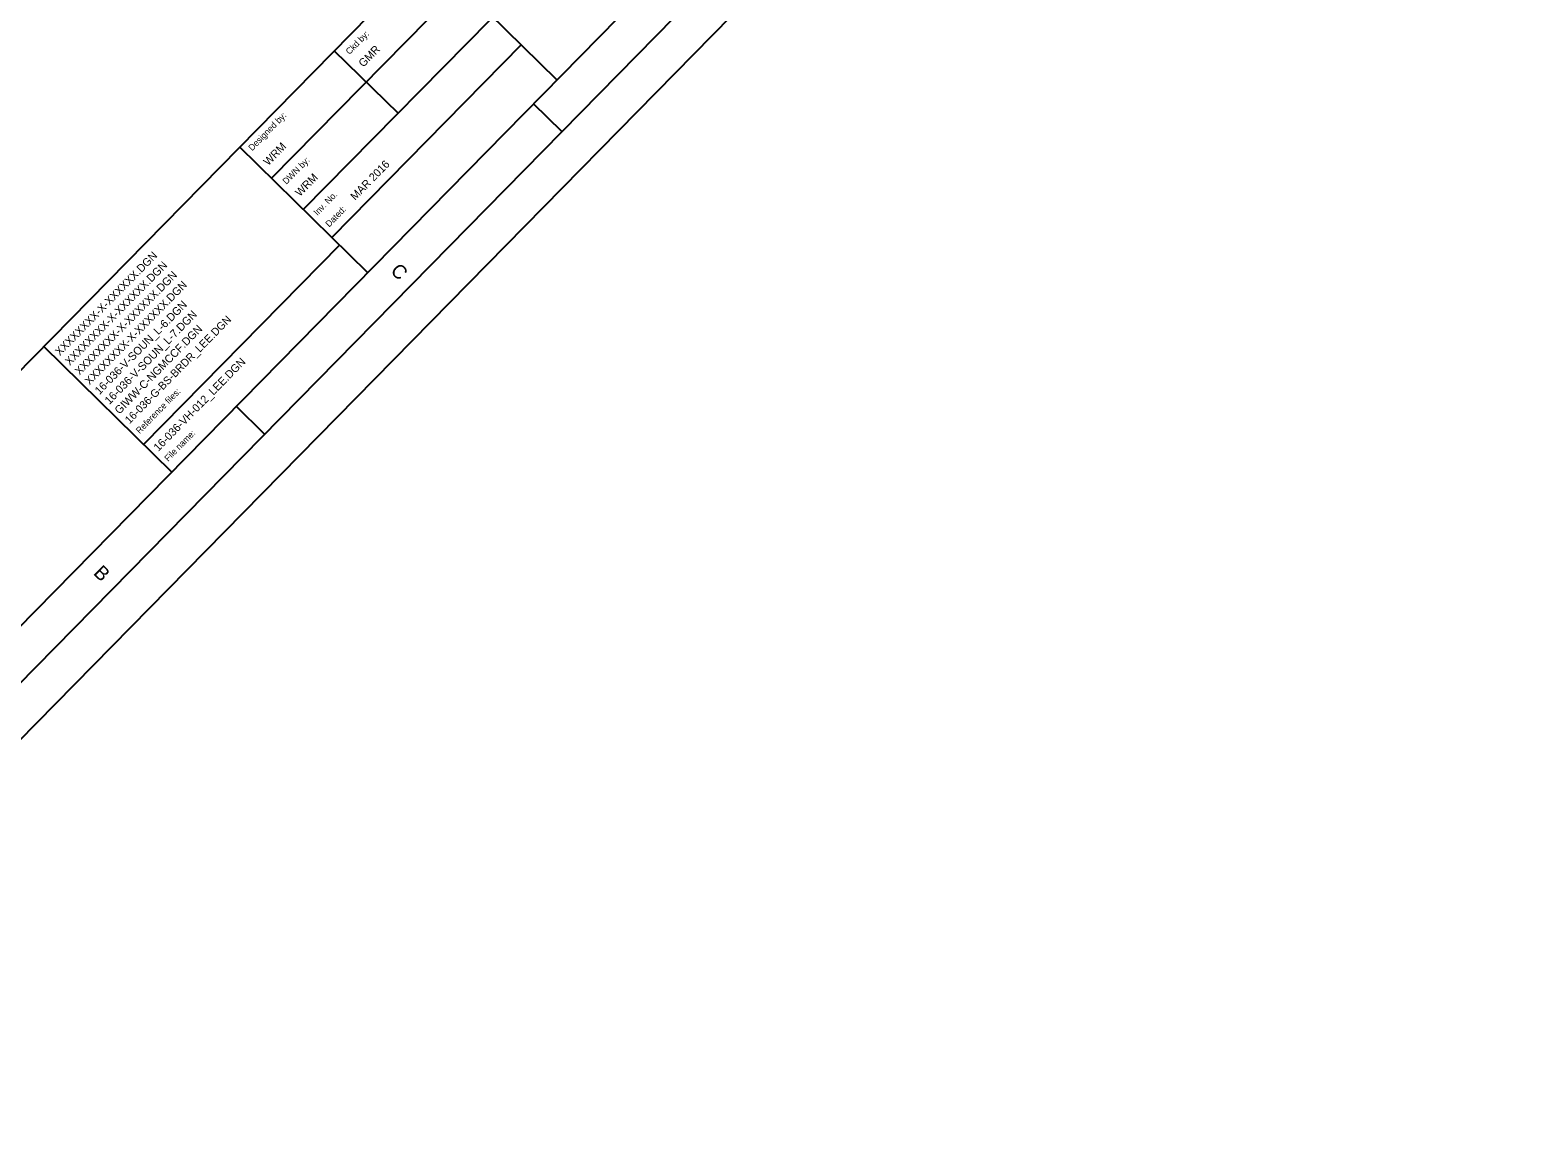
# Model space of a CAD drawing. Extents: x 614899 to 620420, y 778867 to 784376.
# Drawn here: x 618525 to 620420, y 778867 to 780242 of the extents above; entities that cross this region are included whole.
import ezdxf

# ---------------------------------------------------------------- set-up
doc = ezdxf.new("R2010")
doc.units = 0
for name, color, linetype in [('G-ANNO-NPLT', 7, 'Continuous'), ('G-ANNO-TEXT-DRWG', 7, 'Continuous'), ('G-ANNO-TEXT-PROJ', 7, 'Continuous'), ('G-ANNO-TEXT-TTLB', 7, 'Continuous'), ('G-ANNO-TTLB', 7, 'Continuous')]:
    doc.layers.add(name, color=color, linetype=linetype)

msp = doc.modelspace()

# ---------------------------------------------------------------- linework, layer by layer
at = {"layer": 'G-ANNO-NPLT'}
msp.add_lwpolyline([(617282, 784375.7), (620420.5, 781292), (618037.6, 778866.8), (614899.1, 781950.5)], close=True, dxfattribs=at)
at = {"layer": 'G-ANNO-TTLB'}
for p, q in [((620118.6, 781448.4), (617875.8, 779165.9)), ((618868.2, 780016.3), (619471.1, 780629)), ((619026, 780337.5), (619187, 780179.3)), ((618828.4, 780055.6), (619066.6, 780297.6)), ((619142.1, 780223.4), (618904, 779981.1)), ((618906.9, 780216.4), (618987.4, 780137.3)), ((619193.3, 780114.3), (619157.6, 780149.4)), ((618787.6, 780095.5), (618949, 779937)), ((618913.8, 779971.6), (618667.5, 779720.9)), ((618542.2, 779844.1), (618702.7, 779686.4)), ((618819.5, 779733.9), (618783.9, 779769))]:
    msp.add_line(p, q, dxfattribs=at)
for points in [[(614969.8, 781951.2), (618036.9, 778937.5), (620349.8, 781291.3), (617282.6, 784305)], [(620279.1, 781290.7), (617336.7, 784181.8), (615094, 781899.2), (618036.3, 779008.2)]]:
    msp.add_lwpolyline(points, close=True, dxfattribs=at)

# ---------------------------------------------------------------- texts
at = {"layer": 'G-ANNO-TEXT-DRWG'}
for s, p in [('GMR', (618943.8, 780194.6)), ('WRM', (618824.3, 780070.8)), ('WRM', (618864.1, 780032)), ('XXXXXXXX-X-XXXXXX.DGN', (618562.2, 779831.9)), ('XXXXXXXX-X-XXXXXX.DGN', (618574.7, 779819.7)), ('XXXXXXXX-X-XXXXXX.DGN', (618587.1, 779807.4)), ('XXXXXXXX-X-XXXXXX.DGN', (618599.6, 779795.1)), ('16-036-V-SOUN_L-6.DGN', (618612.1, 779782.9)), ('16-036-V-SOUN_L-7.DGN', (618624.6, 779770.6)), ('GIWW-C-NGMCCF.DGN', (618637.1, 779758.3)), ('16-036-VH-012_LEE.DGN', (618686.1, 779711.6))]:
    msp.add_text(s, height=10, rotation=45.5037, dxfattribs=at).set_placement(p)
at = {"layer": 'G-ANNO-TEXT-PROJ'}
for s, height, p in [('MAR 2016', 10, (618933.5, 780027.3)), ('16-036-G-BS-BRDR_LEE.DGN', 9.8, (618649.9, 779746.2))]:
    msp.add_text(s, height=height, rotation=45.5037, dxfattribs=at).set_placement(p)
at = {"layer": 'G-ANNO-TEXT-TTLB'}
for s, p in [('Ckd by:', (618926.4, 780210.5)), ('Designed by:', (618804.1, 780089.5)), ('DWN by:', (618847.1, 780047.3)), ('Inv. No.', (618886, 780008.1)), ('Dated:', (618900.9, 779993.6)), ('Reference files:', (618662.6, 779733.9)), ('File name:', (618698.4, 779699))]:
    msp.add_text(s, height=8, rotation=45.5037, dxfattribs=at).set_placement(p)
at = {"layer": 'G-ANNO-TTLB'}
for s, p in [('C', (618976.9, 779938)), ('B', (618603.5, 779558.3))]:
    msp.add_text(s, height=17.5, rotation=315.5037, dxfattribs=at).set_placement(p)

doc.saveas('drawing.dxf')
